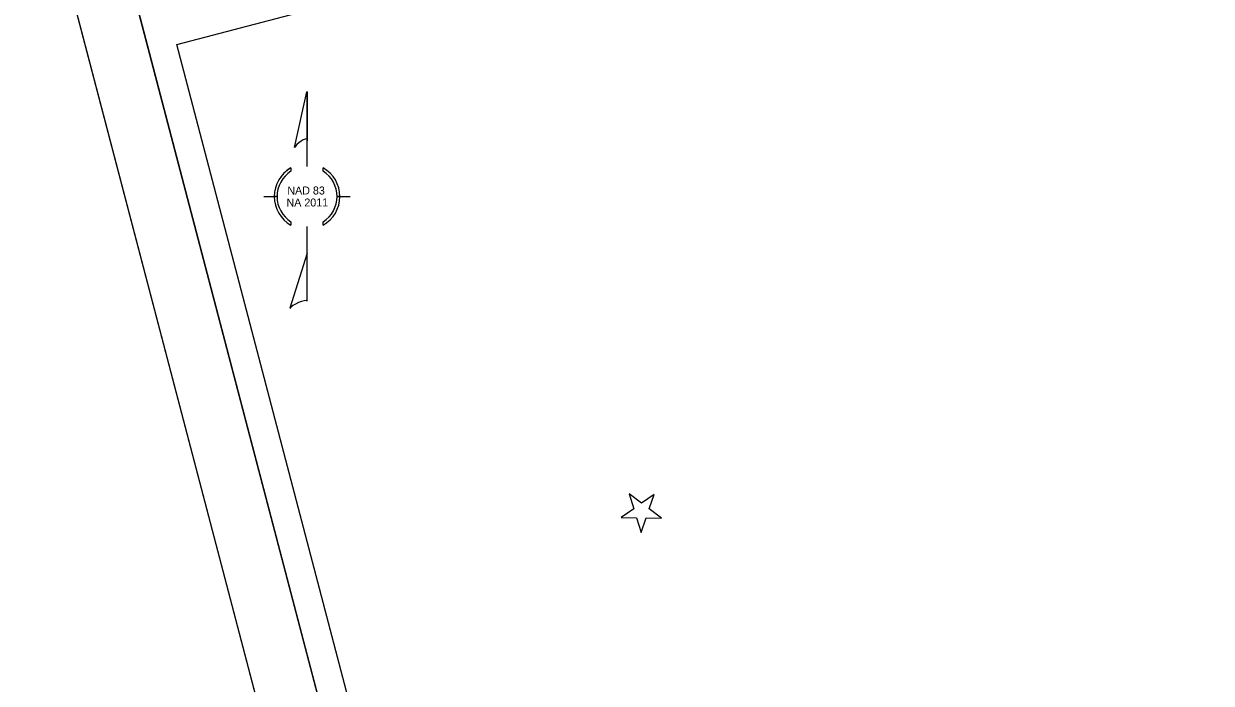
# Model space of a CAD drawing. Extents: x 1366394 to 1367903, y 879298 to 881221.
# Drawn here: x 1366408 to 1367149, y 880397 to 880809 of the extents above; entities that cross this region are included whole.
import ezdxf

# ---------------------------------------------------------------- set-up
doc = ezdxf.new("R2010")
doc.units = 0
for name, color, linetype in [('Exist Hydro Stream or Body of Water Text', 7, 'Continuous'), ('Exist Property Line', 7, 'Continuous'), ('Exist Property Line Text', 7, 'Continuous'), ('Exist Right of Way Line', 7, 'Continuous'), ('Exist Structure Minor Footbridge Terminator', 7, 'Continuous'), ('Scratch_Level_0', 7, 'Continuous'), ('Scratch_Level_4', 7, 'Continuous')]:
    doc.layers.add(name, color=color, linetype=linetype)

msp = doc.modelspace()

# ---------------------------------------------------------------- linework, layer by layer
at = {"layer": 'Exist Hydro Stream or Body of Water Text'}
msp.add_lwpolyline([(1366790.34, 880500.14), (1366793.14, 880490.97), (1366796.27, 880500.04), (1366805.88, 880499.87), (1366798.2, 880505.66), (1366801.33, 880514.74), (1366793.46, 880509.23), (1366785.8, 880515.02), (1366788.6, 880505.83), (1366780.72, 880500.31), (1366790.34, 880500.14)], dxfattribs=at)
at = {"layer": 'Exist Property Line'}
for p, q in [((1366576.57, 880731.52), (1366584.44, 880766.29)), ((1366584.47, 880766.29), (1366584.44, 880766.29)), ((1366584.47, 880766.29), (1366584.44, 880766.29)), ((1366584.47, 880766.29), (1366584.48, 880735.82)), ((1366584.49, 880719.69), (1366584.47, 880766.29)), ((1366584.48, 880735.82), (1366584.48, 880736.68)), ((1366584.48, 880736.68), (1366584.5, 880736.68)), ((1366574.41, 880718.81), (1366574.42, 880718.8)), ((1366574.42, 880718.8), (1366574.42, 880716.75)), ((1366594.59, 880716.74), (1366594.59, 880718.79)), ((1366557.5, 880700.93), (1366565.75, 880700.94)), ((1366565.75, 880700.94), (1366564, 880700.94)), ((1366564, 880700.94), (1366565.75, 880700.94)), ((1366603.25, 880700.95), (1366611.5, 880700.95)), ((1366603.25, 880700.95), (1366605, 880700.95)), ((1366605, 880700.95), (1366603.25, 880700.95)), ((1366574.43, 880685.13), (1366574.43, 880683.08)), ((1366584.52, 880635.59), (1366584.51, 880682.19)), ((1366594.61, 880683.11), (1366594.61, 880685.15)), ((1366594.61, 880683.09), (1366594.61, 880683.11)), ((1366584.49, 880665.59), (1366573.75, 880631.12)), ((1366584.53, 880635.6), (1366584.49, 880665.59))]:
    msp.add_line(p, q, dxfattribs=at)
for radius, start, end in [(20.5, 119.4572, 240.58888), (18.75, 122.5262, 237.51987), (20.5, 299.54346, 60.50262), (20.5, 0.02304, 60.50262), (18.75, 302.62361, 57.42246), (18.75, 0.02304, 57.42246), (20.5, 180.02304, 240.58888), (18.75, 180.02304, 237.51987)]:
    msp.add_arc((1366584.5, 880700.94), radius, start, end, dxfattribs=at)
for centre, major_axis, ratio, start_param, end_param in [((1366580.47, 880733.68), (3.99, 3.06), 0.261723, 6.225794, 8.917625), ((1366584.5, 880700.94), (-0.01, 20.53), 0.998737, 0.514018, 1.570796), ((1366584.5, 880700.94), (-0.01, 18.77), 0.998737, 0.567287, 1.570796), ((1366584.5, 880700.94), (-0.01, 18.77), 0.998737, 3.71058, 4.712389), ((1366584.5, 880700.94), (-0.01, 20.53), 0.998737, 3.657116, 4.712389), ((1366579.14, 880633.17), (5.38, 2.43), 0.225493, 6.280036, 9.220301)]:
    msp.add_ellipse(centre, major_axis=major_axis, ratio=ratio, start_param=start_param, end_param=end_param, dxfattribs=at)
at = {"layer": 'Exist Property Line Text'}
msp.add_line((1366838.49, 879297.82), (1366407.53, 880942.29), dxfattribs=at)
at = {"layer": 'Exist Right of Way Line'}
msp.add_line((1366453.31, 880915.52), (1366865.26, 879343.61), dxfattribs=at)
at = {"layer": 'Exist Structure Minor Footbridge Terminator'}
msp.add_lwpolyline([(1366869.99, 879396.08), (1366503.15, 880795.86), (1367465.82, 881048.15), (1367814.91, 879716.05)], close=True, dxfattribs=at)
at = {"layer": 'Scratch_Level_0'}
msp.add_lwpolyline([(1366865.26, 879343.61), (1366478.66, 880818.79), (1367470.18, 881078.63), (1367856.77, 879603.45)], close=True, dxfattribs=at)
at = {"layer": 'Scratch_Level_4'}
msp.add_lwpolyline([(1366838.49, 879297.82), (1366407.53, 880942.29), (1367471.6, 881221.14), (1367902.56, 879576.68)], close=True, dxfattribs=at)

# ---------------------------------------------------------------- texts
at = {"layer": 'Exist Property Line'}
for s, p in [('NAD 83', (1366572.19, 880702.19)), ('NA 2011', (1366571.65, 880694.69))]:
    msp.add_text(s, height=5, rotation=0.02304, dxfattribs=at).set_placement(p)

doc.saveas('drawing.dxf')
